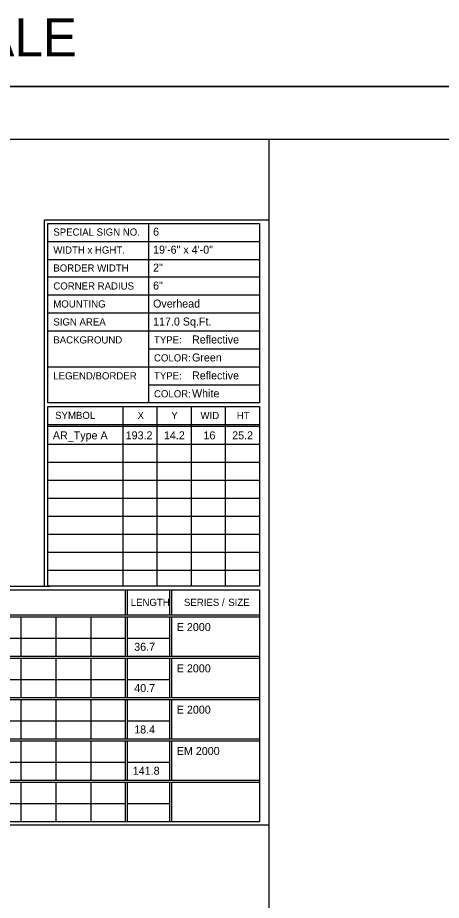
# Model space of a CAD drawing. Extents: x 2149934 to 2150188, y 145114 to 145238.
# Drawn here: x 2150119.2 to 2150146.6, y 145167.4 to 145224.4 of the extents above; entities that cross this region are included whole.
import ezdxf

# ---------------------------------------------------------------- set-up
doc = ezdxf.new("R2010")
doc.units = 0
for name, color, linetype in [('BORDER', 7, 'Continuous'), ('GSSHT', 7, 'Continuous'), ('Level 1', 7, 'Continuous'), ('PDF', 7, 'Continuous'), ('TEXT', 7, 'Continuous')]:
    doc.layers.add(name, color=color, linetype=linetype)

msp = doc.modelspace()

# ---------------------------------------------------------------- linework, layer by layer
at = {"layer": 'BORDER'}
for p, q in [((2150010.458, 145219.948), (2150174.061, 145219.948)), ((2150171.536, 145216.512), (2150017.557, 145216.512))]:
    msp.add_line(p, q, dxfattribs=at)
at = {"layer": 'Level 1'}
for p, q in [((2150135.447, 145216.512), (2150135.447, 145124.606)), ((2150120.969, 145211.34), (2150135.447, 145211.34)), ((2150127.694, 145211.108), (2150127.694, 145199.537)), ((2150121.201, 145209.949), (2150134.843, 145209.949)), ((2150121.201, 145208.789), (2150134.843, 145208.789)), ((2150121.201, 145207.653), (2150134.843, 145207.653)), ((2150121.201, 145206.494), (2150134.843, 145206.494)), ((2150121.201, 145205.334), (2150134.843, 145205.334)), ((2150121.201, 145204.175), (2150134.843, 145204.175)), ((2150127.694, 145203.015), (2150134.843, 145203.015)), ((2150121.201, 145201.856), (2150134.843, 145201.856)), ((2150127.694, 145200.696), (2150134.843, 145200.696)), ((2150121.201, 145187.705), (2150121.201, 145199.305)), ((2150121.201, 145199.305), (2150134.843, 145199.305)), ((2150126.031, 145199.299), (2150126.031, 145198.14)), ((2150128.234, 145199.299), (2150128.234, 145198.14)), ((2150130.437, 145199.299), (2150130.437, 145198.14)), ((2150132.64, 145199.299), (2150132.64, 145198.14)), ((2150134.843, 145199.305), (2150134.843, 145187.705)), ((2150121.201, 145198.14), (2150134.843, 145198.14)), ((2150126.031, 145198.14), (2150126.031, 145187.705)), ((2150128.234, 145198.14), (2150128.234, 145187.705)), ((2150130.437, 145198.14), (2150130.437, 145187.705)), ((2150132.64, 145198.14), (2150132.64, 145187.705)), ((2150121.201, 145198.024), (2150134.843, 145198.024)), ((2150121.201, 145196.864), (2150134.843, 145196.864)), ((2150121.201, 145195.705), (2150134.843, 145195.705)), ((2150121.201, 145194.545), (2150134.843, 145194.545)), ((2150121.201, 145193.386), (2150134.843, 145193.386)), ((2150121.201, 145192.227), (2150134.843, 145192.227)), ((2150121.201, 145191.067), (2150134.843, 145191.067)), ((2150121.201, 145189.908), (2150134.843, 145189.908)), ((2150121.201, 145188.748), (2150134.843, 145188.748)), ((2150076.316, 145187.705), (2150121.342, 145187.705)), ((2150134.843, 145187.705), (2150121.201, 145187.705)), ((2150126.185, 145187.473), (2150126.185, 145185.849)), ((2150126.301, 145187.473), (2150126.301, 145185.849)), ((2150129.048, 145187.473), (2150129.048, 145185.849)), ((2150129.164, 145187.473), (2150129.164, 145185.849)), ((2150076.548, 145185.849), (2150134.843, 145185.849)), ((2150076.548, 145185.733), (2150134.843, 145185.733)), ((2150119.449, 145185.733), (2150119.449, 145183.183)), ((2150121.721, 145185.733), (2150121.721, 145183.183)), ((2150123.97, 145185.733), (2150123.97, 145183.183)), ((2150126.185, 145185.733), (2150126.185, 145183.183)), ((2150126.301, 145185.733), (2150126.301, 145183.183)), ((2150129.048, 145185.733), (2150129.048, 145183.183)), ((2150129.164, 145185.733), (2150129.164, 145183.183)), ((2150076.548, 145184.342), (2150126.185, 145184.342)), ((2150126.301, 145184.342), (2150129.048, 145184.342)), ((2150076.548, 145183.183), (2150134.843, 145183.183)), ((2150076.548, 145183.067), (2150134.843, 145183.067)), ((2150119.449, 145183.067), (2150119.449, 145180.516)), ((2150121.721, 145183.067), (2150121.721, 145180.516)), ((2150123.97, 145183.067), (2150123.97, 145180.516)), ((2150126.185, 145183.067), (2150126.185, 145180.516)), ((2150126.301, 145183.067), (2150126.301, 145180.516)), ((2150129.048, 145183.067), (2150129.048, 145180.516)), ((2150129.164, 145183.067), (2150129.164, 145180.516)), ((2150076.548, 145181.675), (2150126.185, 145181.675)), ((2150126.301, 145181.675), (2150129.048, 145181.675)), ((2150076.548, 145180.516), (2150134.843, 145180.516)), ((2150076.548, 145180.4), (2150134.843, 145180.4)), ((2150119.449, 145180.4), (2150119.449, 145177.849)), ((2150121.721, 145180.4), (2150121.721, 145177.849)), ((2150123.97, 145180.4), (2150123.97, 145177.849)), ((2150126.185, 145180.4), (2150126.185, 145177.849)), ((2150126.301, 145180.4), (2150126.301, 145177.849)), ((2150129.048, 145180.4), (2150129.048, 145177.849)), ((2150129.164, 145180.4), (2150129.164, 145177.849)), ((2150076.548, 145179.008), (2150126.185, 145179.008)), ((2150126.301, 145179.008), (2150129.048, 145179.008)), ((2150076.548, 145177.849), (2150134.843, 145177.849)), ((2150076.548, 145177.733), (2150134.843, 145177.733)), ((2150119.449, 145177.733), (2150119.449, 145175.182)), ((2150121.721, 145177.733), (2150121.721, 145175.182)), ((2150123.97, 145177.733), (2150123.97, 145175.182)), ((2150126.185, 145177.733), (2150126.185, 145175.182)), ((2150126.301, 145177.733), (2150126.301, 145175.182)), ((2150129.048, 145177.733), (2150129.048, 145175.182)), ((2150129.164, 145177.733), (2150129.164, 145175.182)), ((2150076.548, 145176.342), (2150126.185, 145176.342)), ((2150126.301, 145176.342), (2150129.048, 145176.342)), ((2150076.548, 145175.182), (2150134.843, 145175.182)), ((2150076.548, 145175.066), (2150134.843, 145175.066)), ((2150119.449, 145175.066), (2150119.449, 145172.515)), ((2150121.721, 145175.066), (2150121.721, 145172.515)), ((2150123.97, 145175.066), (2150123.97, 145172.515)), ((2150126.185, 145175.066), (2150126.185, 145172.515)), ((2150126.301, 145175.066), (2150126.301, 145172.515)), ((2150129.048, 145175.066), (2150129.048, 145172.515)), ((2150129.164, 145175.066), (2150129.164, 145172.515)), ((2150076.548, 145173.675), (2150126.185, 145173.675)), ((2150126.301, 145173.675), (2150129.048, 145173.675)), ((2150076.548, 145172.515), (2150134.843, 145172.515)), ((2150135.447, 145172.284), (2150076.316, 145172.284))]:
    msp.add_line(p, q, dxfattribs=at)
for points in [[(2150120.969, 145187.705), (2150120.969, 145211.34)], [(2150076.548, 145172.515), (2150076.548, 145187.473), (2150134.843, 145187.473), (2150134.843, 145172.515)]]:
    msp.add_lwpolyline(points, dxfattribs=at)
msp.add_lwpolyline([(2150121.201, 145211.108), (2150134.843, 145211.108), (2150134.843, 145199.537), (2150121.201, 145199.537)], close=True, dxfattribs=at)
at = {"layer": 'PDF'}
msp.add_lwpolyline([(2150010.458, 145114.088), (2150174.061, 145114.088), (2150174.061, 145219.948), (2150010.458, 145219.948)], close=True, dxfattribs=at)

# ---------------------------------------------------------------- texts
at = {"layer": 'GSSHT'}
for s, height, p in [('6', 0.517, (2150127.983, 145210.315)), ('Overhead', 0.5165, (2150127.983, 145205.679))]:
    msp.add_text(s, height=height, dxfattribs=at).set_placement(p)
at = {"layer": 'Level 1'}
for s, height, p in [('SPECIAL SIGN NO.', 0.46374, (2150121.549, 145210.32)), ('WIDTH x HGHT.', 0.46374, (2150121.549, 145209.16)), ('19\'-6" x 4\'-0"', 0.51652, (2150127.983, 145209.156)), ('BORDER WIDTH', 0.46374, (2150121.549, 145208.001)), ('2"', 0.5165, (2150127.983, 145207.997)), ('CORNER RADIUS', 0.46374, (2150121.549, 145206.841)), ('6"', 0.5165, (2150127.983, 145206.838)), ('MOUNTING', 0.4637, (2150121.549, 145205.682)), ('SIGN AREA', 0.4638, (2150121.549, 145204.522)), ('117.0 Sq.Ft.', 0.51652, (2150127.983, 145204.52)), ('BACKGROUND', 0.4637, (2150121.549, 145203.363)), ('TYPE:', 0.4637, (2150128.042, 145203.363)), ('Reflective', 0.5165, (2150130.494, 145203.361)), ('COLOR:', 0.4637, (2150128.042, 145202.203)), ('Green', 0.5165, (2150130.494, 145202.203)), ('LEGEND/BORDER', 0.46374, (2150121.549, 145201.044)), ('TYPE:', 0.4637, (2150128.042, 145201.044)), ('Reflective', 0.5165, (2150130.494, 145201.044)), ('COLOR:', 0.4637, (2150128.042, 145199.885)), ('White', 0.5165, (2150130.494, 145199.885)), ('SYMBOL', 0.4637, (2150121.665, 145198.493)), ('X', 0.464, (2150126.981, 145198.488)), ('Y', 0.464, (2150129.161, 145198.488)), ('WID', 0.4637, (2150131.04, 145198.488)), ('HT', 0.4637, (2150133.382, 145198.488)), ('AR_Type A', 0.5165, (2150121.52, 145197.177)), ('193.2', 0.5165, (2150126.216, 145197.177)), ('14.2', 0.5165, (2150128.683, 145197.177)), ('16', 0.5165, (2150131.233, 145197.177)), ('25.2', 0.5165, (2150133.084, 145197.177)), ('LENGTH', 0.4638, (2150126.541, 145186.429)), ('LENGTH', 0.4638, (2150126.541, 145186.429)), ('SERIES /', 0.4638, (2150129.975, 145186.429)), ('SIZE', 0.4638, (2150132.832, 145186.429)), ('E 2000', 0.5165, (2150129.512, 145184.81)), ('36.7', 0.5165, (2150126.768, 145183.535)), ('E 2000', 0.5165, (2150129.512, 145182.145)), ('40.7', 0.5165, (2150126.768, 145180.87)), ('E 2000', 0.5165, (2150129.512, 145179.479)), ('18.4', 0.5165, (2150126.766, 145178.204)), ('EM 2000', 0.5165, (2150129.512, 145176.814)), ('141.8', 0.5165, (2150126.674, 145175.539))]:
    msp.add_text(s, height=height, dxfattribs=at).set_placement(p)
at = {"layer": 'TEXT'}
msp.add_text('BORDER AND REPORT 70 SCALE', height=2.46401, dxfattribs=at).set_placement((2150070.157, 145221.883))

doc.saveas('drawing.dxf')
